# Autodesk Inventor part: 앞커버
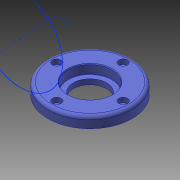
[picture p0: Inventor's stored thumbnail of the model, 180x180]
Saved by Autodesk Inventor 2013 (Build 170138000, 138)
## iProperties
Created: 2010-03
Part Number: 앞커버
Document SubType Name: Modeling
Designer: 진현석
Density: 1 g/cm^3
Material: 알루미늄 6061
Author: 진현석
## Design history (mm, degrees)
sketch "스케치1"
  geometry: C1 r 38 at (0, 0); 1 further point
  constraints: 1 centre point, 1 coincident
  dimensions: "d56" = 76 diameter of C1
extrude "돌출1" new body sketch "스케치1" distance "d0" = 10; taper "d1" = 0 deg
sketch "스케치2"
  geometry: C1 r 26 at (0, 0); C2 r 38 at (0, 0) reference
  constraints: 1 centre point, 1 concentric
  dimensions: "d51" = 52 diameter of C1
extrude "돌출3" join sketch "스케치2" distance "d4" = 3; taper "d5" = 0 deg
sketch "스케치4"
  geometry: C1 r 38 at (0, 0) reference; C2 r 15 at (0, 0)
  constraints: 1 centre point, 1 coincident
  dimensions: "d22" = 30 diameter of C2
extrude "돌출5" cut sketch "스케치4" stored distance "d23" = 10; taper "d24" = 0 deg
sketch "스케치6"
  geometry: C1 r 38 at (0, 0) reference; 1 further point
  constraints: 1 vertical alignment
  dimensions: "d32" = 30 distance of C1.centre point (0, 30)
hole "구멍2" sketch "스케치6" at (0, 30) diameter "d33" = 4.5; stored, may be unused: countersink angle "d37" = 90 deg, drill point angle "d39" = 118 deg; dims "d34" = 6, "d35" = 8, "d36" = 4.4, "d38" = 8
sketch "스케치7"
  geometry: C1 r 38 at (0, 0) reference; C2 r 20 at (0, 0)
  constraints: 1 centre point, 1 coincident
  dimensions: "d43" = 40 diameter of C2
extrude "돌출7" cut sketch "스케치7" distance "d44" = 8.3; taper "d45" = 0 deg
chamfer "모따기2" distance "d46" = 0.8; stored, may be unused: second distance "d47" = 2, angle "d48" = 30 deg
fillet "모깎기2" dims "d49" = 0.3
fillet "모깎기3" dims "d50" = 3
chamfer "모따기3" distance "d53" = 1; stored, may be unused: second distance "d54" = 2, angle "d55" = 45 deg
node "솔리드1"
pattern_circular "원형 패턴2" dims angle "d41" = 360 deg
